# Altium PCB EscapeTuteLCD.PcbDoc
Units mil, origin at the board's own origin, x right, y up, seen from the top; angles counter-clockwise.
Board outline 3350 x 4485 mil, 2 copper layers (Top Layer, Bottom Layer); 16 components, 24 nets, 76 pads, 13 vias.
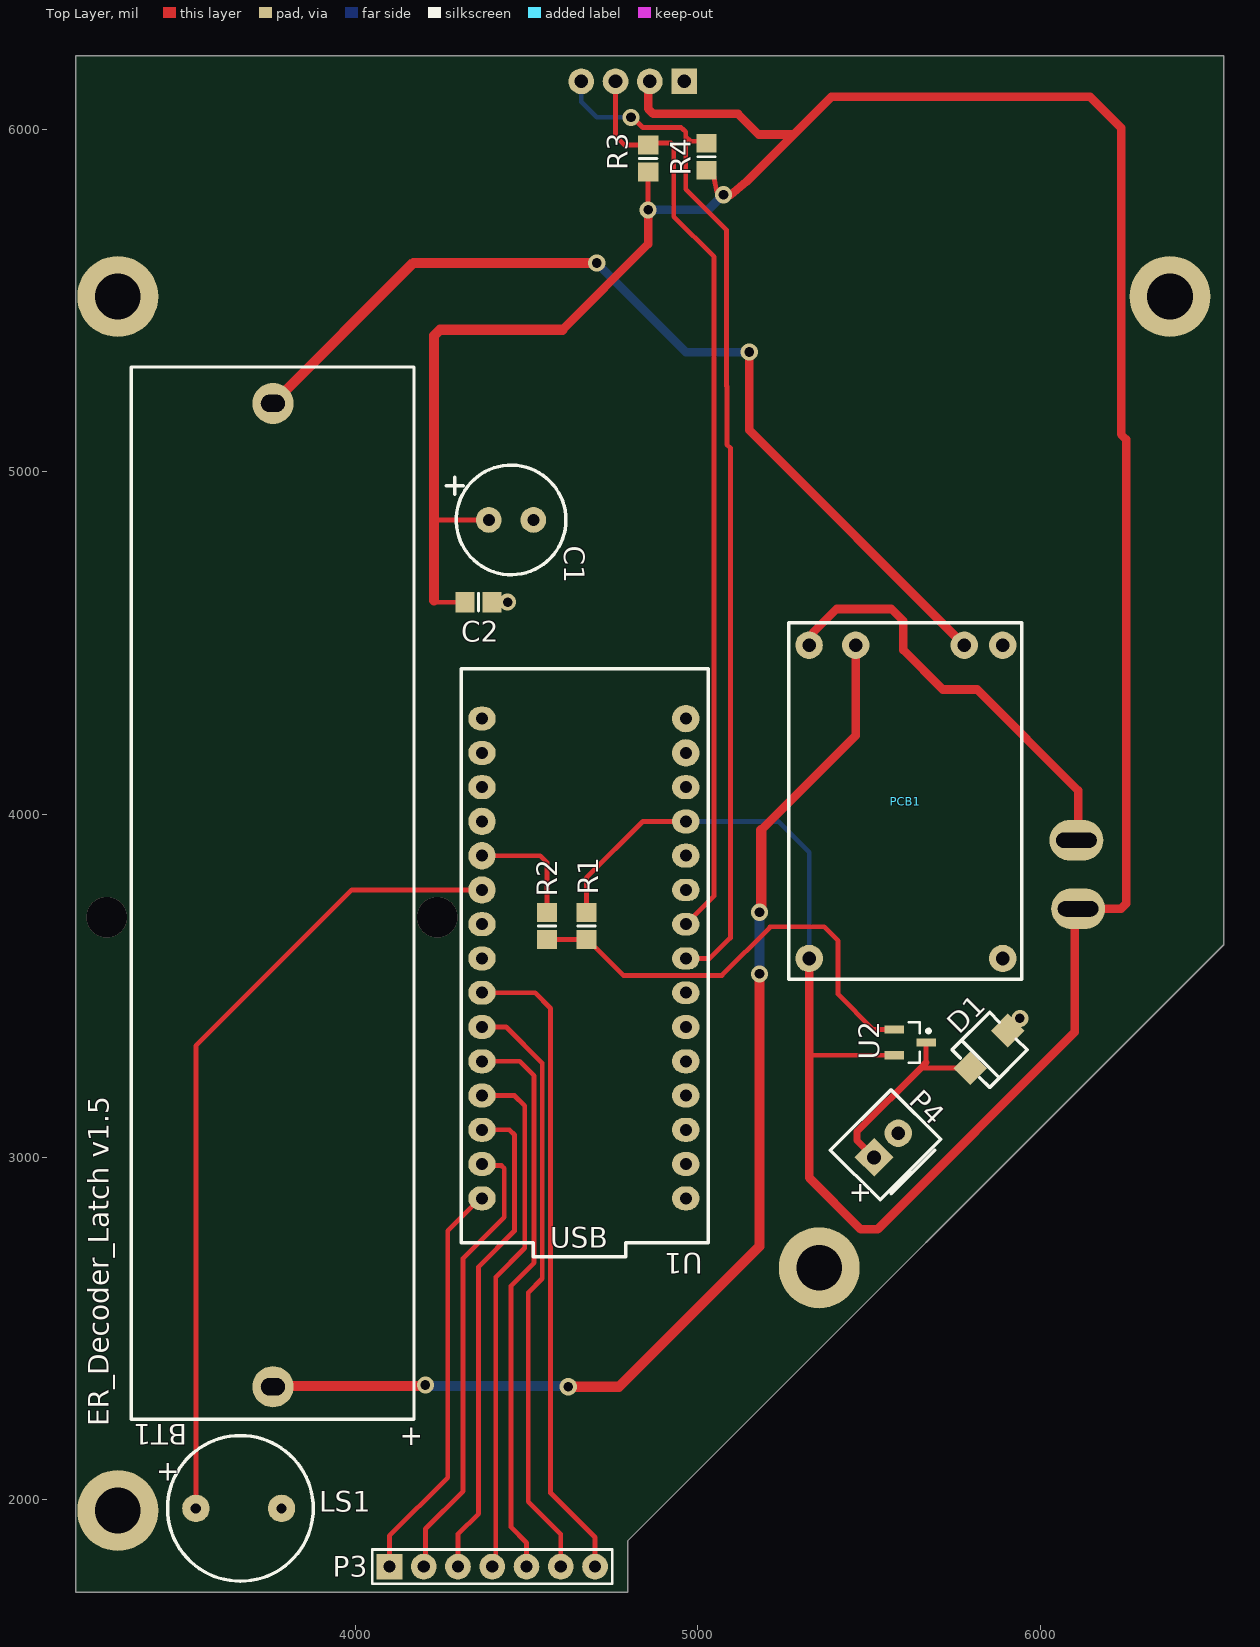
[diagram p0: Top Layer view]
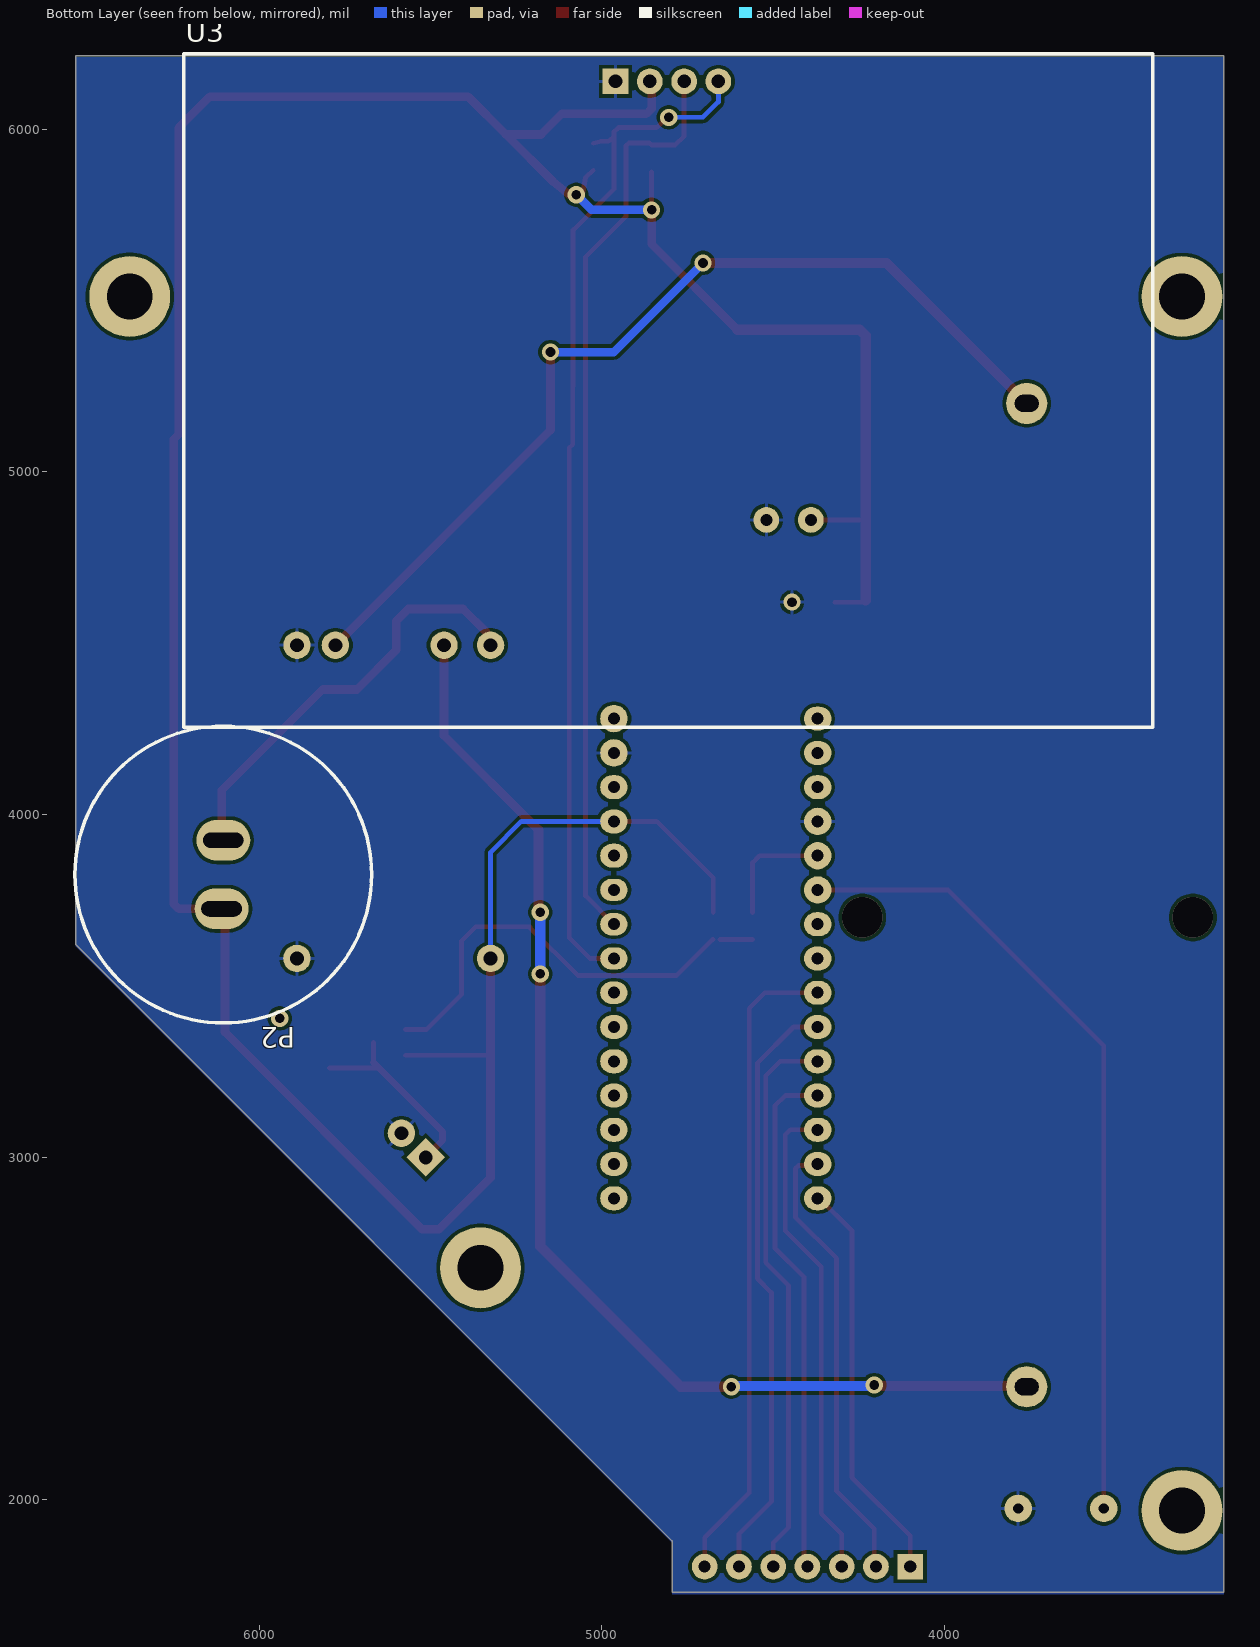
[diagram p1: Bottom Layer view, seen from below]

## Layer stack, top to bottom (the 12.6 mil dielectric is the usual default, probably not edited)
Top Solder: solder mask 0.4, Solder Resist, Dk 3.5
Top Layer: signal copper 1.4
Dielectric 1: dielectric 12.6, FR-4, Dk 4.8
Bottom Layer: signal copper 1.4
Bottom Solder: solder mask 0.4, Solder Resist, Dk 3.5

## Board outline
3185,1730 3185,6215 6535,6215 6535,3620 4795,1880 4795,1730

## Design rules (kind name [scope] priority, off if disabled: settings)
Clearance [All] p1: gap=10 ignorepadtopadclearanceinfootprint=FALSE except(0: Arc-Hole Track-Hole SMDPad-Hole THPad-Hole Via-Hole Fill-Hole Poly-Hole Region-Hole Text-Hole)
PolygonConnect [All] p1: connectstyle=Relief reliefconductorwidth=10 reliefentries=4 polygonreliefangle="90 Angle" airgapwidth=10
RoutingVias [All] p1: holewidth=28 width=50 viastyle="Through Hole" minholewidth=28 minwidth=50 maxholewidth=28 maxwidth=50
SolderMaskExpansion [All] p1: expansion=4 istentingtop=FALSE
SupplyNets "Schematic Supply Nets_3" [InNet('Latch')] p1: voltage=0.000
SupplyNets "Schematic Supply Nets_2" [InNet('Vcc')] p2: voltage=0.000
SupplyNets "Schematic Supply Nets_1" [InNet('GND')] p3: voltage=0.000
SupplyNets "Schematic Supply Nets" [InNet('VBatt')] p4: voltage=0.000
Width [All] p1: maxlimit=30 minlimit=12 preferedwidth=14
30 further rules are at their usual default settings.

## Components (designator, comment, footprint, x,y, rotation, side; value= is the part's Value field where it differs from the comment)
BT1 "Battery" Batt_18650 3346.61,5306.38 r270 top
C1 "Cap Pol1" Cap220uF 4390,4860 r0 top value=100uF
C2 "Cap" 6-0805_M 4360,4620 r180 top value=100nF
D1 "LCSC: C8678" DIODE_SCHOTTKY 5904.6,3369.6 r225 top
LS1 "Speaker" PIEZO 3785,1975 r270 top
P2 "KeySwitch" KeySwitch 6105,3825 r270 bottom
P3 "KeyPadModule" HDR1X7 4100,1805 r0 top
P4 "Solenoid" JST_2Way_2.5mmPitch 5514.29,2999.29 r45 top
PCB1 "LiIonCharger1S" CHARGER18650 5945,3520 r90 top
R1 "100K" 6-0805_M 4675,3675 r270 top
R2 "1K" 6-0805_M 4560,3675 r270 top
R3 "5K" 6-0805_M 4855,5915 r270 top value=100K
R4 "5K" 6-0805_M 5025,5920 r270 top value=100K
U1 "ArduinoNano" ArduinoNano -43595,-42445 r0 top
U2 "AO3415" SOT23_M 5620,3335 r0 top value=AO3015
U3 "OLED_Screen" OLED_Screen_2.54Inch 4810,6140 r180 bottom

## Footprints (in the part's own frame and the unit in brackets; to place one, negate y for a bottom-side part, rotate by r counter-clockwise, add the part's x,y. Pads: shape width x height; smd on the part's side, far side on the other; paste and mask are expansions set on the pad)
6-0805_M [mm] "Chip Resistor, Body 2.0x1.2mm, IPC Low Density"
  rect 1.4x1.5 smd: 1(-1,0) 2(1,0)
  silkscreen extent 0,-0.65 0,0.65, body extent -1.07,-0.7 1.07,0.7, height 0.7
ArduinoNano [mil]
  oval 80x70 hole 35: 1(47965,46725) 2(47965,46625) 3(47965,46525) 7(47965,46125) 8(47965,46025) 9(47965,45925) 10(47965,45825) 11(47965,45725) 12(47965,45625) 13(47965,45525) 14(47965,45425) 15(47965,45325) 16(48560,45325) 17(48560,45425) 18(48560,45525) 19(48560,45625) 20(48560,45725) 21(48560,45825) 26(48560,46325) 27(48560,46425) 28(48560,46525)
  round 80 hole 35: 4(47965,46425) 5(47965,46325) 6(47965,46225) 29(48560,46625) 30(48560,46725)
  oval 80x65 hole 35: 22(48560,45925) 23(48560,46025) 24(48560,46125) 25(48560,46225)
  silkscreen extent 47905,45155 48625,46870
Batt_18650 [mil]
  round 120 hole 50 slot 70 at 90 deg: 1(106.3,413.39) 2(2976.38,413.39)
  silkscreen extent 0,0 3071,825
Cap220uF [mil]
  round 75 hole 35: 1(0,0) 2(130,0)
  silkscreen extent -125,-160 225,160
CHARGER18650 [mil]
  round 80 hole 40: 1(60,620) 2(60,55) 3(974.41,620.08) 4(974.41,484.25) 5(974.41,167.32) 6(974.41,55.12)
  silkscreen extent 0,0 1040,680
DIODE_SCHOTTKY [mil]
  rect 70x70 smd: 1(155,0) 2(0,0)
  silkscreen extent 0,-75 155,80
HDR1X7 [mm] "Connector; Header; 7 Position"
  rect 1.905x1.905 hole 0.9: 1(0,0)
  round 1.905 hole 0.9: 2(2.54,0) 3(5.08,0) 4(7.62,0) 5(10.16,0) 6(12.7,0) 7(15.24,0)
  silkscreen extent -1.27,-1.27 16.51,1.27
JST_2Way_2.5mmPitch [mil]
  rect 80x80 hole 40: 1(0,0)
  round 80 hole 40: 2(100,0)
  silkscreen extent -75,-110 175,105
KeySwitch [mm]
  oval 3x4 hole 1.143 slot 3 at 90 deg: 1(-2.54,0) 2(2.54,-0.127)
  silkscreen extent -11,-11 11,11
OLED_Screen_2.54Inch [mil]
  rect 75x75 hole 40: 1(-150,0)
  round 75 hole 40: 2(-50,0) 3(50,0) 4(150,0)
  silkscreen extent -1410,-1885 1417,80
PIEZO [mil]
  round 80 hole 30: 1(0,0) 2(0,-250)
  silkscreen extent -213,-333 213,93
SOT23_M [mm] "SOT23, 3-Leads, Body 2.9x1.3mm, Pitch 0.95mm, Lead Span 2.3mm - Reverse Pinning, IPC Low Density"
  rect 1.45x0.6 smd: 1(-1.175,0.95) 2(-1.175,-0.95) 3(1.175,0)
  silkscreen extent -0.1,-1.5 1.48,1.5, body extent -0.7,-1.5 0.7,1.5, height 1.1

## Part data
BT1: "Multicell Battery"
C1: "Polarized Capacitor (Radial)"
C2: "Capacitor"
D1: library part "Diode 10TQ035", "Schottky Rectifier"
LS1: "Loudspeaker"
P2 P4: library part "Header 2", "Header, 2-Pin"
P3: library part "Header 7", "Header, 7-Pin"
R1 R3 R4: library part RC0603FR-07100KL, "RES SMD 100K OHM 1% 1/10W 0603"
R2: library part RC0603FR-071KL, "RES SMD 1 KOHM 1% 1/10W 0603"
U2: "MOSFET P-CH 20V 4A SOT23", MFR="Alpha & Omega Semiconductor Inc."

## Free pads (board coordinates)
  round 236.22 hole 133.86: 0(3307.09,1968.5) 0(3307.09,5511.81) 0(5354.33,2677.17) 0(6377.95,5511.81)

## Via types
v1: diameter 50, hole 28, Top Layer to Bottom Layer, 11 vias
v2: diameter 118.11, hole 118.11, Top Layer to Bottom Layer, 2 vias

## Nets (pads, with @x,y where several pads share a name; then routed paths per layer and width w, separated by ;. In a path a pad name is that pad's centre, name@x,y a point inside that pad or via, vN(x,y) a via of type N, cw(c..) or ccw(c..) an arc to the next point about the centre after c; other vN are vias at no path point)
DB4: U1.19
DB5: U1.20
DB6: U1.21
DB7: U1.22
E: U1.7
GND: C1.2 C2.1 LS1.1 P4.2 PCB1.2 PCB1.6 U1.4 U1.29 U3.1
  other v1: 4445,4620
Latch: D1.1 P4.1 U2.3 | length 583
  Top Layer w14: 5652.5,3262.5 5655,3260 D1.1 ; 5666.26,3276.26 U2.3
  Top Layer w20: P4.1 5465,3048.58 5465,3075 5652.5,3262.5 5666.26,3276.26
NetBT1_1: BT1.1 PCB1.5 | length 2798.5
  Top Layer w25: v1(5150,5350) 5150,5122.09 PCB1.5
  Top Layer w30: BT1.1 4169.92,5610 v1(4705,5610)
  Bottom Layer w14: BT1.1 BT1.1@3770.92,5189.16
  Bottom Layer w25: v1(4705,5610) 4965,5350 v1(5150,5350)
NetBT1_2: BT1.2 PCB1.4 | length 3464.7
  Top Layer w14: v1(5180,3715) v1@5185,3720 ; 5185,3955 5190,3960
  Top Layer w25: 5190,3960 5460.75,4230.75 PCB1.4
  Top Layer w30: BT1.2 3762.5,2332.5 4202.5,2332.5 v1(4205,2335) ; v1(4622,2330) 4770,2330 5180,2740 v1(5180,3535) ; v1@5185,3720 5185,3955
  Bottom Layer w30: v1(4205,2335) 4207.5,2332.5 4619.5,2332.5 v1(4622,2330) ; v1(5180,3535) v1(5180,3715)
NetLS1_2: LS1.2 U1.6 | length 2383.5
  Top Layer w14: LS1.2 3535,3325 3990,3780 U1.6
  Bottom Layer w14: LS1.2 LS1.2@3535,1985.04
NetP3_1: P3.1 U1.15 | length 1189.8
  Top Layer w14: P3.1 4100,1895 4270,2065 4270,2785 4365,2880 U1.15
NetP3_2: P3.2 U1.14 | length 1330
  Top Layer w14: P3.2 4205.25,1810.25 4205.25,1915.25 4315,2025 4315,2705 4435,2825 4435,2967.4 4426.8,2975.6 4374.4,2975.6 U1.14
NetP3_3: P3.3 U1.13 | length 1429.6
  Top Layer w14: P3.3 4300,1900 4360,1960 4360,2680 4465,2785 4465,3065 4450,3080 U1.13
NetP3_4: P3.4 U1.12 | length 1521.8
  Top Layer w14: U1.12 4465,3180 4495,3150 4495,2735 4410,2650 4410,1815 P3.4
NetP3_5: P3.5 U1.11 | length 1648.8
  Top Layer w14: U1.11 4480,3280 4522,3238 4522,2692 4455,2625 4455,1920 4500,1875 P3.5
NetP3_6: P3.6 U1.10 | length 1745.7
  Top Layer w14: U1.10 4440.74,3380 4546,3274.74 4546,2646 4505,2605 4505,1995 4600,1900 P3.6
NetP3_7: P3.7 U1.9 | length 1902.5
  Top Layer w14: U1.9 4525,3480 4570,3435 4570,2020 4700,1890 P3.7
NetR1_2: R1.2 R2.2 U2.1 | length 1313.2
  Top Layer w14: R2.2 R1.2@4655,3635.63 ; R1.2 4676.97,3635.63 4782.1,3530.5 5070.5,3530.5 5210,3670 5210,3672.4 5368.74,3672.4 5409.37,3631.77 5409.37,3475.63 5512.6,3372.4 U2.1
RS: U1.8
SCL: R3.1 U1.24 U3.3 | length 2701
  Top Layer w14: U3.3 4760,5980 4785.63,5954.37 R3.1 4860.63,5960 4921.8,5960 4930,5951.8 4930,5745 5047.5,5627.5 5047.5,3762.5 U1.24
SDA: R4.1 U1.23 U3.4 | length 3028.3
  Top Layer w14: v1(4805,6035) 4810.05,6035 4840.05,6005 4951.8,6005 4955.9,6000.9 4965,5992.58 4965,5978.71 ; U1.23 5035,3580 5095,3640 5095,5070 5085,5080 5085,5249.5 5084,5250.5 5084,5706 4965,5825 4965,5978.71 ; R4.1 5002.47,5965 4980,5965 4965,5978.71
  Bottom Layer w14: U3.4 4660,6080 4705,6035 v1(4805,6035)
SolenoidActuate: R2.1 U1.5 | length 343.9
  Top Layer w14: U1.5 4540,3880 4560,3860 R2.1
VBATT: P2.1 PCB1.3 | length 1248.3
  Top Layer w14: PCB1.3 5337.55,4507.04 5337.55,4532.55
  Top Layer w25: 5337.55,4532.55 5405,4600 5565,4600 5600,4565 5600,4480 5715,4365 5815.31,4365 6110,4070.31 P2.1@6110,3935
VCC: C1.1 C2.2 P2.2 PCB1.1 R1.1 R3.2 R4.2 U1.27 U2.2 U3.2 | length 10069.9
  Top Layer w14: 4230,4625 4235,4620 C2.2 ; 4230,4860 C1.1 ; R1.1 4675,3815 4840,3980 U1.27 ; v1(4855,5765) R3.2 ; R4.2 5047.53,5860.07 5055.15,5817.15 5063.35,5808.95 v1(5074.95,5808.95) ; 5325,3290 5332.6,3297.6 U2.2
  Top Layer w25: 4605,5415 4855,5665 v1(4855,5765) ; U3.2 4855,6135 4855,6060 4870,6045 5117.5,6045 5177.5,5985 5280,5985 ; v1(5074.95,5808.95) 5095.66,5808.95 5141.77,5846.77 5280,5985 ; PCB1.1 5325,3290 5325,2940 5475,2790 5525,2790 6100,3365 P2.2@6100,3725 ; P2.2 6235.36,3725 6250,3739.64 6250,5095 6235.36,5109.64 6235.36,6004.64 6145,6095 5390,6095 5280,5985
  Top Layer w30: 4230,4625 4230,4860 4230,5397.43 4247.57,5415 4605,5415
  Bottom Layer w14: U1.27 5235,3980 5325,3890 PCB1.1
  Bottom Layer w25: v1(4855,5765) 5030.51,5765 5074.46,5808.95 v1(5074.95,5808.95)
pads on no net: D1.2 U1.1 U1.2 U1.3 U1.16 U1.17 U1.18 U1.25 U1.26 U1.28 U1.30
copper on no net:
  other v1: 5940,3405
  other v2: 3275,3700 4240,3700

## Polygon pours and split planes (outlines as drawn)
GND on Bottom Layer "GND_L02_P000" (solid, pour order 0): 3185,1725 4795,1725 4795,1875 6535,3615 6535,6210 3185,6210

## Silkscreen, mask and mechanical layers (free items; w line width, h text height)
Top Overlay:
  text "+" at 5440,2870 h60
  text "ER_Decoder_Latch v1.5" at 3280,2215 h60 r90
  text "+" at 4130,2160 h60
  text "+" at 3420,2055 h60
Mechanical 1:
  the board outline again, w14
